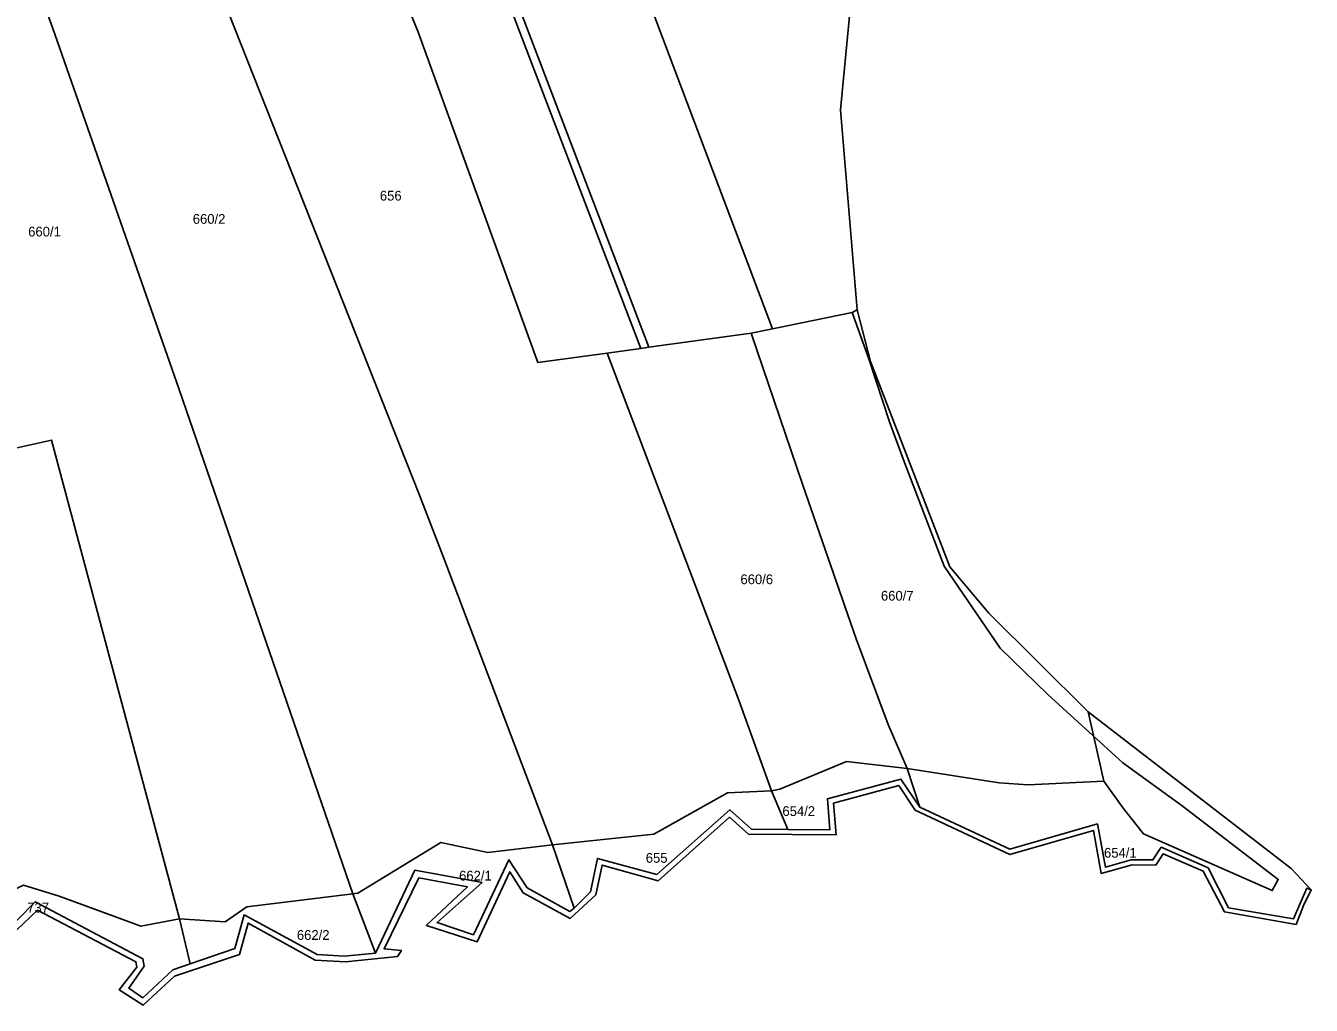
# Model space of a CAD drawing. Extents: x -629983 to -626385, y -1072828 to -1067897.
# Drawn here: x -627472.6 to -627077.3, y -1071291.1 to -1070989.8 of the extents above; entities that cross this region are included whole.
import ezdxf

# ---------------------------------------------------------------- set-up
doc = ezdxf.new("R2010")
doc.units = 0
for name, color, linetype in [('Parcela nároku', 7, 'Continuous'), ('Parcelní číslo', 7, 'Continuous'), ('Plocha PÚ', 7, 'Continuous'), ('Převzatý obvod_Vraclav', 7, 'Continuous'), ('Šetřený obvod', 7, 'Continuous')]:
    doc.layers.add(name, color=color, linetype=linetype)

msp = doc.modelspace()

# ---------------------------------------------------------------- linework, layer by layer
at = {"layer": 'Parcela nároku'}
for points in [[(-627324.65, -1070869.98), (-627282.97, -1070860.49), (-627274.55, -1070858.83), (-627254.24, -1070852.32), (-627237.3, -1070846.31), (-627227.43, -1070840.51), (-627234.72, -1070849.27), (-627225.38, -1070887.83), (-627217.27, -1070965.31), (-627222.05, -1071015.66), (-627216.92, -1071077.12), (-627218.51, -1071078), (-627242.92, -1071082.98), (-627278.49, -1070988.8), (-627304.36, -1070919.55), (-627314.21, -1070895.06)], [(-627425.39, -1071101.61), (-627464.39, -1070990.31), (-627494.83, -1070907.68), (-627511.34, -1070863.62), (-627558.97, -1070852.76), (-627563.32, -1070867.25), (-627565.13, -1070881.01), (-627553.22, -1070912.19), (-627487.28, -1071091.1), (-627484.82, -1071098.49), (-627477.62, -1071120.08), (-627464.68, -1071117.19), (-627425.29, -1071264.47), (-627411.23, -1071265.41), (-627404.64, -1071260.81), (-627372.04, -1071256.74)], [(-627511.34, -1070863.62), (-627458.27, -1070875.13), (-627414.24, -1070975.53), (-627351.5, -1071134.14), (-627344.19, -1071153.05), (-627310.58, -1071241.74), (-627330.46, -1071244.09), (-627344.95, -1071240.94), (-627370.43, -1071256.59), (-627372.04, -1071256.74), (-627425.39, -1071101.61), (-627464.39, -1070990.31), (-627494.83, -1070907.68)], [(-627243.27, -1071225.13), (-627253.31, -1071197.18), (-627293.78, -1071090.43), (-627315.1, -1071093.36), (-627352.03, -1070991.41), (-627397.15, -1070881.84), (-627416.76, -1070883.94), (-627458.27, -1070875.13), (-627414.24, -1070975.53), (-627351.5, -1071134.14), (-627344.19, -1071153.05), (-627310.58, -1071241.74), (-627279.45, -1071238.38), (-627256.78, -1071225.7)], [(-627334.65, -1070955.19), (-627351.59, -1070907.93), (-627364.95, -1070877.04), (-627378.98, -1070876.68), (-627383.46, -1070880.08), (-627397.15, -1070881.84), (-627352.03, -1070991.41), (-627315.1, -1071093.36), (-627293.78, -1071090.43), (-627283.43, -1071089)], [(-627314.21, -1070895.06), (-627304.36, -1070919.55), (-627278.49, -1070988.8), (-627242.92, -1071082.98), (-627249.56, -1071084.34), (-627281.03, -1071088.67), (-627323.76, -1070976.6), (-627348.99, -1070906.83), (-627337.88, -1070902.81)], [(-627348.99, -1070906.83), (-627323.76, -1070976.6), (-627281.03, -1071088.67), (-627283.43, -1071089), (-627334.65, -1070955.19), (-627351.59, -1070907.93)], [(-627190.18, -1071156.03), (-627202.32, -1071124.14), (-627206.9, -1071111.85), (-627213.35, -1071092.2), (-627218.51, -1071078), (-627242.92, -1071082.98), (-627249.56, -1071084.34), (-627233.61, -1071131.06), (-627217.24, -1071178.38), (-627207.42, -1071204.66), (-627201.52, -1071218.23), (-627173.21, -1071222.67), (-627164.31, -1071223.2), (-627141.08, -1071222.13), (-627135.09, -1071230.45), (-627128.87, -1071238.35), (-627089.28, -1071255.75), (-627087.45, -1071252.31), (-627116.97, -1071229.75), (-627135.19, -1071216.5), (-627158.25, -1071195.42), (-627172.91, -1071181.19)], [(-627141.08, -1071222.13), (-627135.09, -1071230.45), (-627128.87, -1071238.35), (-627089.28, -1071255.75), (-627087.45, -1071252.31), (-627116.97, -1071229.75), (-627135.19, -1071216.5), (-627158.25, -1071195.42), (-627172.91, -1071181.19), (-627190.18, -1071156.03), (-627202.32, -1071124.14), (-627206.9, -1071111.85), (-627213.35, -1071092.2), (-627218.51, -1071078), (-627216.92, -1071077.12), (-627212.8, -1071093.03), (-627188.43, -1071156.17), (-627176.47, -1071170.42), (-627145.9, -1071200.79), (-627083.42, -1071248.96), (-627077.27, -1071255.55), (-627078.6, -1071255), (-627080.76, -1071259.93), (-627082.71, -1071264.5), (-627102.74, -1071261.03), (-627108.99, -1071248.78), (-627123.42, -1071242.44), (-627125.97, -1071246.33), (-627132.64, -1071246.29), (-627140.56, -1071248.56), (-627143.03, -1071235.24), (-627169.97, -1071242.98), (-627197.66, -1071230.16), (-627201.52, -1071218.23), (-627173.21, -1071222.67), (-627164.31, -1071223.2)], [(-627217.24, -1071178.38), (-627233.61, -1071131.06), (-627249.56, -1071084.34), (-627281.03, -1071088.67), (-627283.43, -1071089), (-627293.78, -1071090.43), (-627253.31, -1071197.18), (-627243.27, -1071225.13), (-627240.69, -1071224.57), (-627220.16, -1071216.07), (-627201.52, -1071218.23), (-627207.42, -1071204.66)], [(-627243.27, -1071225.13), (-627240.69, -1071224.57), (-627220.16, -1071216.07), (-627201.52, -1071218.23), (-627197.66, -1071230.16), (-627203.46, -1071221.46), (-627226.09, -1071227.54), (-627225.29, -1071237.04), (-627238.26, -1071236.93)], [(-627238.26, -1071236.93), (-627243.27, -1071225.13), (-627256.78, -1071225.7), (-627279.45, -1071238.38), (-627310.58, -1071241.74), (-627303.99, -1071261.21), (-627298.94, -1071256.15), (-627296.79, -1071245.87), (-627278.5, -1071250.8), (-627256.08, -1071230.92), (-627249.41, -1071236.83)], [(-627498.79, -1071255.3), (-627486.91, -1071260.34), (-627473.28, -1071254.08), (-627462.29, -1071257.52), (-627437.2, -1071266.71), (-627425.29, -1071264.47), (-627422, -1071278.29), (-627427.34, -1071280.11), (-627436.56, -1071288.74), (-627440.85, -1071285.81), (-627436.15, -1071279.05), (-627436.55, -1071276.75), (-627469.7, -1071259.18), (-627480.25, -1071269.95), (-627497.11, -1071267.41), (-627512, -1071255.35), (-627505.96, -1071250.1), (-627506.7, -1071244.71), (-627523.08, -1071239.28), (-627524.91, -1071234.88), (-627507.1, -1071242.82), (-627500.58, -1071252.88)], [(-627310.58, -1071241.74), (-627303.99, -1071261.21), (-627305.24, -1071262.17), (-627318.44, -1071254.92), (-627323.99, -1071246.27), (-627334.94, -1071269.35), (-627346.13, -1071265.6), (-627332.27, -1071253.33), (-627352.95, -1071249.51), (-627365.05, -1071274.99), (-627372.04, -1071256.74), (-627370.43, -1071256.59), (-627344.95, -1071240.94), (-627330.46, -1071244.09)], [(-627411.23, -1071265.41), (-627404.64, -1071260.81), (-627372.04, -1071256.74), (-627365.05, -1071274.99), (-627374.68, -1071275.89), (-627383.02, -1071275.41), (-627405.48, -1071263.23), (-627408.32, -1071273.62), (-627422, -1071278.29), (-627425.29, -1071264.47)]]:
    msp.add_lwpolyline(points, close=True, dxfattribs=at)
for points in [[(-627477.62, -1071120.08), (-627464.68, -1071117.19), (-627425.29, -1071264.47), (-627437.2, -1071266.71), (-627462.29, -1071257.52), (-627473.28, -1071254.08)], [(-627480.25, -1071269.95), (-627469.7, -1071259.18), (-627436.55, -1071276.75), (-627436.15, -1071279.05), (-627440.85, -1071285.81), (-627436.56, -1071288.74), (-627427.34, -1071280.11), (-627422, -1071278.29), (-627408.32, -1071273.62), (-627405.48, -1071263.23), (-627383.02, -1071275.41), (-627374.68, -1071275.89), (-627365.05, -1071274.99), (-627352.95, -1071249.51), (-627332.27, -1071253.33), (-627346.13, -1071265.6), (-627334.94, -1071269.35), (-627323.99, -1071246.27), (-627318.44, -1071254.92), (-627305.24, -1071262.17), (-627303.99, -1071261.21), (-627298.94, -1071256.15), (-627296.79, -1071245.87), (-627278.5, -1071250.8), (-627256.08, -1071230.92), (-627249.41, -1071236.83), (-627238.26, -1071236.93), (-627225.29, -1071237.04), (-627226.09, -1071227.54), (-627203.46, -1071221.46), (-627197.66, -1071230.16), (-627169.97, -1071242.98), (-627143.03, -1071235.24), (-627140.56, -1071248.56), (-627132.64, -1071246.29), (-627125.97, -1071246.33), (-627123.42, -1071242.44), (-627108.99, -1071248.78), (-627102.74, -1071261.03), (-627082.71, -1071264.5), (-627080.76, -1071259.93), (-627078.6, -1071255), (-627077.27, -1071255.55), (-627079.62, -1071260.36), (-627081.97, -1071266.19), (-627103.96, -1071262.31), (-627110.49, -1071249.75), (-627122.82, -1071244.44), (-627125.1, -1071247.95), (-627132.36, -1071247.83), (-627141.9, -1071250.49), (-627144.27, -1071237.25), (-627170.02, -1071244.72), (-627199.09, -1071231.07), (-627204.07, -1071223.44), (-627224.24, -1071228.9), (-627223.4, -1071238.58), (-627250.36, -1071238.39), (-627256.14, -1071233.2), (-627278.11, -1071252.72), (-627295.39, -1071247.95), (-627297.29, -1071257.05), (-627305.14, -1071264.31), (-627319.59, -1071256.46), (-627323.74, -1071249.99), (-627333.76, -1071271.53), (-627349.35, -1071266.49), (-627349.39, -1071266.39), (-627336.76, -1071254.58), (-627351.73, -1071251.89), (-627362.4, -1071273.66), (-627357.05, -1071274.24), (-627358.27, -1071276.09), (-627374.26, -1071277.66), (-627383.63, -1071277.12), (-627404.24, -1071265.75), (-627406.88, -1071275.4), (-627426.84, -1071282.05), (-627436.54, -1071291.05), (-627443.88, -1071286.27), (-627438.4, -1071279.37), (-627438.72, -1071277.66), (-627468.97, -1071261.76), (-627479.62, -1071271.95)]]:
    msp.add_lwpolyline(points, dxfattribs=at)
at = {"layer": 'Plocha PÚ'}
for points in [[(-627220.16, -1071216.07), (-627201.52, -1071218.23), (-627173.21, -1071222.67), (-627164.31, -1071223.2), (-627141.08, -1071222.13), (-627145.9, -1071200.79), (-627145.9, -1071200.79), (-627176.47, -1071170.42), (-627188.43, -1071156.17), (-627212.8, -1071093.03), (-627216.92, -1071077.12), (-627222.05, -1071015.66), (-627217.27, -1070965.31)], [(-627473.28, -1071254.08), (-627462.29, -1071257.52), (-627449.74, -1071262.12), (-627437.2, -1071266.71), (-627425.29, -1071264.47), (-627411.23, -1071265.41), (-627404.64, -1071260.81), (-627372.04, -1071256.74), (-627370.43, -1071256.59), (-627344.95, -1071240.94), (-627330.46, -1071244.09), (-627310.58, -1071241.74), (-627279.45, -1071238.38), (-627256.78, -1071225.7), (-627243.27, -1071225.13), (-627240.69, -1071224.57), (-627220.16, -1071216.07)]]:
    msp.add_lwpolyline(points, dxfattribs=at)
at = {"layer": 'Převzatý obvod_Vraclav'}
msp.add_lwpolyline([(-627217.27, -1070965.31), (-627222.05, -1071015.66), (-627216.92, -1071077.12), (-627212.8, -1071093.03), (-627188.43, -1071156.17), (-627176.47, -1071170.42), (-627145.9, -1071200.79)], dxfattribs=at)
at = {"layer": 'Šetřený obvod'}
for p, q in [((-627141.08, -1071222.13), (-627145.9, -1071200.79)), ((-627240.69, -1071224.57), (-627220.16, -1071216.07)), ((-627220.16, -1071216.07), (-627201.52, -1071218.23)), ((-627279.45, -1071238.38), (-627256.78, -1071225.7)), ((-627256.78, -1071225.7), (-627243.27, -1071225.13)), ((-627243.27, -1071225.13), (-627240.69, -1071224.57)), ((-627310.58, -1071241.74), (-627279.45, -1071238.38)), ((-627370.43, -1071256.59), (-627344.95, -1071240.94)), ((-627344.95, -1071240.94), (-627330.46, -1071244.09)), ((-627330.46, -1071244.09), (-627310.58, -1071241.74)), ((-627404.64, -1071260.81), (-627372.04, -1071256.74)), ((-627372.04, -1071256.74), (-627370.43, -1071256.59)), ((-627411.23, -1071265.41), (-627404.64, -1071260.81)), ((-627437.2, -1071266.71), (-627425.29, -1071264.47)), ((-627425.29, -1071264.47), (-627411.23, -1071265.41))]:
    msp.add_line(p, q, dxfattribs=at)
for points in [[(-627201.52, -1071218.23), (-627173.21, -1071222.67), (-627164.31, -1071223.2), (-627141.08, -1071222.13)], [(-627473.28, -1071254.08), (-627462.29, -1071257.52), (-627437.2, -1071266.71)]]:
    msp.add_lwpolyline(points, dxfattribs=at)

# ---------------------------------------------------------------- texts
at = {"layer": 'Parcelní číslo'}
for s, p in [('656', (-627363.7, -1071043.53)), ('660/2', (-627421.24, -1071050.68)), ('660/1', (-627471.85, -1071054.58)), ('660/6', (-627252.82, -1071161.53)), ('660/7', (-627209.61, -1071166.58)), ('654/2', (-627239.91, -1071232.82)), ('654/1', (-627141.01, -1071245.65)), ('655', (-627281.93, -1071247.21)), ('662/1', (-627339.33, -1071252.68)), ('737', (-627472.15, -1071262.51)), ('662/2', (-627389.22, -1071270.93))]:
    msp.add_text(s, height=3, dxfattribs=at).set_placement(p)

doc.saveas('drawing.dxf')
